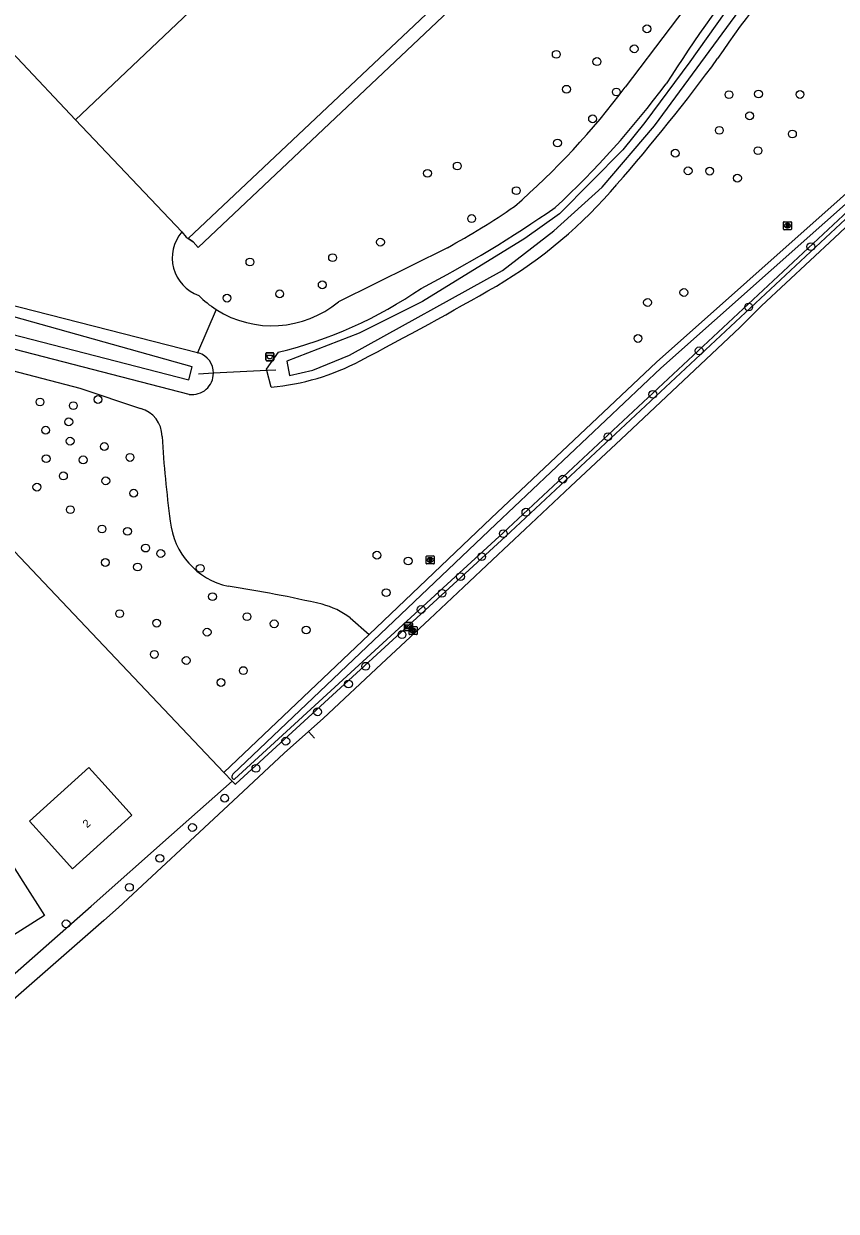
# Model space of a CAD drawing. Extents: x 156651 to 158072, y 387631 to 388990.
# Drawn here: x 157693.9 to 157795.5, y 388128.4 to 388276.8 of the extents above; entities that cross this region are included whole.
import ezdxf

# ---------------------------------------------------------------- set-up
doc = ezdxf.new("R2010")
doc.units = 0
for name, color, linetype in [('IMGEO_Afvalbak', 7, 'Continuous'), ('IMGEO_Boom', 7, 'Continuous'), ('IMGEO_Brandkraan', 7, 'Continuous'), ('IMGEO_Duiker', 7, 'Continuous'), ('IMGEO_Erf', 7, 'Continuous'), ('IMGEO_Grasland_overig', 7, 'Continuous'), ('IMGEO_Greppel_droge_sloot', 7, 'Continuous'), ('IMGEO_Groenvoorziening', 7, 'Continuous'), ('IMGEO_Hek', 7, 'Continuous'), ('IMGEO_Loofbos', 7, 'Continuous'), ('IMGEO_Pand', 7, 'Continuous'), ('IMGEO_Pand_nummerreeks', 7, 'Continuous'), ('IMGEO_Rijbaan_lokaal_gesloten', 7, 'Continuous'), ('IMGEO_Rijbaan_lokaal_open', 7, 'Continuous'), ('IMGEO_Rioolput', 7, 'Continuous'), ('IMGEO_Verklikker', 7, 'Continuous'), ('IMGEO_Waterloop', 7, 'Continuous')]:
    doc.layers.add(name, color=color, linetype=linetype)

msp = doc.modelspace()

# ---------------------------------------------------------------- linework, layer by layer
at = {"layer": 'IMGEO_Afvalbak'}
for p, q in [((157724.2, 388234.74), (157724.2, 388235.54)), ((157724.2, 388235.54), (157724.2, 388234.74)), ((157724.3, 388235.64), (157725.09, 388235.64)), ((157725.09, 388235.64), (157724.3, 388235.64)), ((157725.19, 388235.54), (157725.19, 388234.74)), ((157725.19, 388234.74), (157725.19, 388235.54)), ((157725.09, 388234.64), (157724.3, 388234.64)), ((157724.3, 388234.64), (157725.09, 388234.64))]:
    msp.add_line(p, q, dxfattribs=at)
msp.add_lwpolyline([(157724.34, 388235.35), (157725.05, 388235.35), (157724.9, 388234.88), (157724.49, 388234.88), (157724.34, 388235.35)], dxfattribs=at)
for centre, start, end in [((157724.3, 388235.54), 90, 180), ((157724.3, 388235.54), 90, 180), ((157725.09, 388235.54), 0, 90), ((157725.09, 388235.54), 360, 90), ((157724.3, 388234.74), 180, 270), ((157724.3, 388234.74), 180, 270), ((157725.09, 388234.74), 270, 0), ((157725.09, 388234.74), 270, 0)]:
    msp.add_arc(centre, 0.1, start, end, dxfattribs=at)
at = {"layer": 'IMGEO_Boom'}
for centre in [(157771.82, 388276.12), (157770.23, 388273.62), (157760.49, 388272.93), (157765.57, 388272.03), (157761.77, 388268.57), (157768, 388268.23), (157782.07, 388267.9), (157785.77, 388267.98), (157790.95, 388267.92), (157765.03, 388264.87), (157784.65, 388265.25), (157780.87, 388263.43), (157790, 388262.98), (157760.65, 388261.86), (157775.36, 388260.58), (157785.7, 388260.9), (157748.12, 388258.98), (157744.4, 388258.07), (157776.97, 388258.37), (157779.66, 388258.34), (157783.13, 388257.46), (157755.49, 388255.9), (157749.92, 388252.41), (157738.52, 388249.46), (157792.3, 388248.9), (157722.21, 388246.98), (157732.54, 388247.52), (157731.25, 388244.13), (157719.35, 388242.47), (157725.92, 388243), (157776.44, 388243.17), (157771.9, 388241.92), (157784.53, 388241.36), (157770.7, 388237.43), (157778.35, 388235.88), (157772.55, 388230.44), (157695.98, 388229.49), (157700.14, 388229.03), (157703.22, 388229.8), (157696.68, 388225.96), (157699.57, 388227), (157699.74, 388224.6), (157766.96, 388225.16), (157704.02, 388223.92), (157696.75, 388222.4), (157701.37, 388222.25), (157707.22, 388222.56), (157698.9, 388220.25), (157695.59, 388218.85), (157704.2, 388219.63), (157761.32, 388219.85), (157707.68, 388218.09), (157699.77, 388216.03), (157756.7, 388215.71), (157703.73, 388213.61), (157706.91, 388213.32), (157753.87, 388213.03), (157709.17, 388211.23), (157711.07, 388210.55), (157738.08, 388210.34), (157741.99, 388209.61), (157751.17, 388210.15), (157704.14, 388209.43), (157708.17, 388208.86), (157716, 388208.7), (157748.53, 388207.66), (157717.54, 388205.16), (157739.23, 388205.66), (157746.21, 388205.57), (157743.61, 388203.55), (157705.93, 388203.04), (157721.85, 388202.66), (157710.55, 388201.85), (157716.86, 388200.72), (157725.24, 388201.77), (157729.24, 388201), (157741.21, 388200.42), (157710.26, 388197.94), (157714.25, 388197.18), (157736.68, 388196.46), (157721.39, 388195.92), (157718.59, 388194.43), (157734.52, 388194.25), (157730.66, 388190.76), (157726.69, 388187.1), (157722.96, 388183.7), (157719.05, 388179.97), (157715.03, 388176.31), (157710.95, 388172.46), (157707.15, 388168.84), (157699.24, 388164.28)]:
    msp.add_circle(centre, 0.489, dxfattribs=at)
at = {"layer": 'IMGEO_Brandkraan'}
for p, q in [((157742.1, 388200.49), (157742.1, 388201.34)), ((157742.17, 388201.41), (157743.02, 388201.41)), ((157742.59, 388201.19), (157742.61, 388201.19)), ((157743.1, 388201.34), (157743.1, 388200.49)), ((157743.02, 388200.41), (157742.17, 388200.41)), ((157742.61, 388200.63), (157742.58, 388200.63))]:
    msp.add_line(p, q, dxfattribs=at)
for points in [[(157742.1, 388200.49), (157742.1, 388201.34)], [(157742.17, 388201.41), (157743.02, 388201.41)], [(157742.44, 388201.11), (157742.44, 388200.71), (157742.66, 388200.71)], [(157742.68, 388201.11), (157742.44, 388201.11)], [(157743.1, 388201.34), (157743.1, 388200.49)], [(157743.02, 388200.41), (157742.17, 388200.41)], [(157742.62, 388201.03), (157742.57, 388201.03), (157742.57, 388200.96)], [(157742.57, 388200.96), (157742.62, 388200.96)], [(157742.63, 388200.88), (157742.57, 388200.88), (157742.57, 388200.8)], [(157742.57, 388200.8), (157742.63, 388200.8)]]:
    msp.add_lwpolyline(points, dxfattribs=at)
for centre, radius, start, end in [((157742.17, 388201.34), 0.0765, 91.552, 178.448), ((157742.17, 388201.34), 0.0765, 91.552, 178.448), ((157742.68, 388200.97), 0.145, 59.4692, 91.5367), ((157742.71, 388201.02), 0.0922, 285.5137, 58.1501), ((157743.02, 388201.34), 0.0765, 1.552, 88.448), ((157743.02, 388201.34), 0.0765, 1.552, 88.448), ((157742.17, 388200.49), 0.0765, 181.552, 268.448), ((157742.17, 388200.49), 0.0765, 181.552, 268.448), ((157742.62, 388200.99), 0.0379, 267.8285, 90.9355), ((157742.63, 388200.84), 0.0404, 269.8759, 90.5077), ((157742.66, 388200.96), 0.251, 268.6676, 293.5347), ((157742.71, 388200.82), 0.105, 301.3115, 78.989), ((157743.02, 388200.49), 0.0765, 271.552, 358.448), ((157743.02, 388200.49), 0.0765, 271.552, 358.448)]:
    msp.add_arc(centre, radius, start, end, dxfattribs=at)
for centre, major_axis, ratio, start_param, end_param in [((157742.58, 388200.91), (-0.387, 0.002), 0.722429, 4.712389, 7.853982), ((157742.61, 388200.91), (-0.39, 0.002), 0.717154, 1.570796, 4.712389)]:
    msp.add_ellipse(centre, major_axis=major_axis, ratio=ratio, start_param=start_param, end_param=end_param, dxfattribs=at)
at = {"layer": 'IMGEO_Duiker'}
msp.add_lwpolyline([(157725.44, 388233.48), (157724.34, 388233.42), (157723.48, 388233.38), (157717.66, 388233.08), (157715.8, 388232.98)], dxfattribs=at)
at = {"layer": 'IMGEO_Erf'}
msp.add_lwpolyline([(157720.01, 388182.1), (157718.96, 388183.18)], dxfattribs=at)
at = {"layer": 'IMGEO_Grasland_overig'}
msp.add_lwpolyline([(157714.48, 388249.93), (157742.73, 388276.53), (157772, 388304.24)], dxfattribs=at)
at = {"layer": 'IMGEO_Greppel_droge_sloot'}
for points in [[(157898.22, 388349.88), (157896.12, 388347.95), (157883.14, 388335.24), (157875.62, 388328.26), (157850.32, 388304.57), (157824.42, 388280.31), (157812.24, 388268.91), (157807.84, 388264.16), (157773.56, 388233.71), (157752.92, 388214.22), (157737.66, 388199.69), (157720.09, 388182.97)], [(157720.27, 388182.34), (157753.86, 388213.13), (157808.21, 388263.87), (157812.84, 388268.47), (157850.82, 388304.16)]]:
    msp.add_lwpolyline(points, dxfattribs=at)
for centre, radius, start, end in [((157720.84, 388182.47), 0.906, 146.5853, 171.9999), ((157720.23, 388182.62), 0.284, 185.1845, 278.9201)]:
    msp.add_arc(centre, radius, start, end, dxfattribs=at)
at = {"layer": 'IMGEO_Groenvoorziening'}
for points in [[(157720.01, 388182.1), (157720.37, 388181.71), (157720.45, 388181.78), (157754.16, 388212.68), (157808.51, 388263.42), (157813.13, 388268.02), (157851.11, 388303.71), (157859.17, 388311.3), (157875.96, 388327.05), (157883.96, 388334.28), (157889.9, 388339.8), (157897.83, 388347.26), (157900.24, 388349.53), (157900.45, 388349.74), (157900.08, 388350.11), (157899.45, 388350.76), (157898.68, 388351.56)], [(157737.09, 388200.43), (157752.35, 388214.95), (157773, 388234.45), (157807.27, 388264.9), (157811.67, 388269.65), (157823.85, 388281.05), (157849.76, 388305.31), (157875.06, 388329), (157882.58, 388335.98), (157895.55, 388348.69), (157898.68, 388351.56)], [(157714.63, 388230.44), (157681.86, 388238.86)], [(157680.96, 388236.41), (157700.97, 388231.21), (157708.54, 388228.69)], [(157715.66, 388235.65), (157715.78, 388235.62)], [(157724.87, 388231.33), (157724.34, 388233.42), (157724.3, 388233.57), (157725.76, 388235.71)], [(157718.96, 388183.18), (157670.96, 388233.81)], [(157734.72, 388202.5), (157737.09, 388200.43)], [(157737.09, 388200.43), (157718.96, 388183.18)], [(157691.12, 388156.56), (157702.36, 388166.5), (157712.43, 388175.4), (157720.01, 388182.1)]]:
    msp.add_lwpolyline(points, dxfattribs=at)
for centre, radius, start, end in [((157868.74, 388213.66), 105.88, 135.6314, 146.3009), ((157962.63, 388148.26), 223.91, 142.1451, 147.2893), ((157594.17, 388408.93), 231.12, 318.7989, 323.7926), ((157682.33, 388337.68), 114.57, 312.9233, 323.3326), ((157723.08, 388294.68), 58.88, 300.5528, 319.8157), ((157671.2, 388382.45), 156.53, 297.5526, 304.7184), ((157712.97, 388288.42), 54.23, 283.6398, 304.4018), ((157497.79, 388689.21), 513.2, 297.6555, 299.8223), ((157715, 388233.08), 2.66, 359.9979, 72.8569), ((157722.25, 388260.5), 29.28, 275.133, 297.9998), ((157714.99, 388233.08), 2.66, 262.1888, 0.0084), ((157707.61, 388225.19), 3.62, 359.9494, 75.0421), ((157847.53, 388232.98), 136.52, 183.2751, 187.7468), ((157721.52, 388215.55), 9.32, 185.9724, 257.459), ((157697.89, 388062.38), 145.69, 76.7663, 81.4691), ((157728.98, 388195.17), 9.31, 51.9482, 75.9543)]:
    msp.add_arc(centre, radius, start, end, dxfattribs=at)
at = {"layer": 'IMGEO_Hek'}
for points in [[(157714.48, 388249.93), (157715.11, 388249.5), (157715.75, 388248.8), (157773.13, 388303.04)], [(157700.43, 388264.76), (157713.69, 388250.74)], [(157713.69, 388250.74), (157714.23, 388250.09), (157714.48, 388249.93)]]:
    msp.add_lwpolyline(points, dxfattribs=at)
at = {"layer": 'IMGEO_Loofbos'}
for points in [[(157772, 388304.24), (157773.13, 388303.04), (157715.75, 388248.8), (157715.11, 388249.5), (157714.48, 388249.93)], [(157780.36, 388283.71), (157769.12, 388268.84)], [(157700.43, 388264.76), (157713.69, 388250.74)], [(157713.69, 388250.74), (157714.23, 388250.09), (157714.48, 388249.93)], [(157746.88, 388248.77), (157733.27, 388242.01)], [(157715.66, 388235.65), (157678.64, 388245.1)], [(157717.99, 388241.05), (157715.66, 388235.65)]]:
    msp.add_lwpolyline(points, dxfattribs=at)
for centre, radius, start, end in [((157693.03, 388325.62), 94.94, 310.9512, 323.2697), ((157698.75, 388336.43), 100.01, 298.7674, 304.4049), ((157717.52, 388247.5), 5.02, 139.7833, 250.0185), ((157724.99, 388252.04), 13.03, 225.2117, 237.4879), ((157724.97, 388252.01), 13, 237.5051, 309.712)]:
    msp.add_arc(centre, radius, start, end, dxfattribs=at)
at = {"layer": 'IMGEO_Pand'}
for points in [[(157692.42, 388273.24), (157660.73, 388306.77), (157663.25, 388309.16), (157664.82, 388307.49), (157679.51, 388321.39), (157677.94, 388323.06), (157678.7, 388323.78), (157680.26, 388322.13), (157683.43, 388325.13), (157684.77, 388323.72), (157685.77, 388324.68), (157722.55, 388285.76), (157700.43, 388264.76)], [(157700.43, 388264.76), (157693.11, 388272.51), (157692.42, 388273.24)], [(157702.08, 388183.8), (157704.1, 388181.57), (157707.46, 388177.86), (157700.05, 388171.16), (157696.69, 388174.86), (157694.66, 388177.09), (157702.08, 388183.8)], [(157689.82, 388175.84), (157693.83, 388169.55), (157696.52, 388165.33), (157691.88, 388162.37), (157689.19, 388166.58), (157685.17, 388172.87), (157689.82, 388175.84)]]:
    msp.add_lwpolyline(points, dxfattribs=at)
at = {"layer": 'IMGEO_Rijbaan_lokaal_gesloten'}
for points in [[(157901.9, 388350.55), (157898.23, 388346.86), (157851.76, 388303.15), (157795.28, 388250), (157786.13, 388241.5), (157783.41, 388238.79), (157768.62, 388224.85), (157762.28, 388218.91), (157756.59, 388213.58), (157752.53, 388209.75), (157748.88, 388206.34), (157744.63, 388202.35), (157738.66, 388196.76), (157731.37, 388189.93), (157729.53, 388188.29)], [(157729.53, 388188.29), (157730.29, 388187.49)]]:
    msp.add_lwpolyline(points, dxfattribs=at)
at = {"layer": 'IMGEO_Rijbaan_lokaal_open'}
msp.add_lwpolyline([(157729.53, 388188.29), (157726.48, 388185.59), (157719.5, 388179.05), (157705.8, 388166.31), (157703.95, 388164.69), (157659.96, 388126.22)], dxfattribs=at)
at = {"layer": 'IMGEO_Rioolput'}
for p, q in [((157788.88, 388251.09), (157788.88, 388251.95)), ((157788.95, 388252.02), (157789.81, 388252.02)), ((157789.37, 388251.8), (157789.39, 388251.8)), ((157789.88, 388251.95), (157789.88, 388251.09)), ((157789.81, 388251.02), (157788.95, 388251.02)), ((157789.39, 388251.24), (157789.37, 388251.24)), ((157744.23, 388209.32), (157744.23, 388210.17)), ((157744.31, 388210.25), (157745.16, 388210.25)), ((157744.72, 388210.03), (157744.75, 388210.03)), ((157745.24, 388210.17), (157745.24, 388209.32)), ((157745.16, 388209.25), (157744.31, 388209.25)), ((157744.74, 388209.47), (157744.72, 388209.47))]:
    msp.add_line(p, q, dxfattribs=at)
for points in [[(157788.88, 388251.09), (157788.88, 388251.95)], [(157788.95, 388252.02), (157789.81, 388252.02)], [(157789.47, 388251.72), (157789.22, 388251.72), (157789.22, 388251.32)], [(157789.4, 388251.64), (157789.34, 388251.64), (157789.34, 388251.56)], [(157789.34, 388251.56), (157789.39, 388251.56)], [(157789.88, 388251.95), (157789.88, 388251.09)], [(157789.81, 388251.02), (157788.95, 388251.02)], [(157789.22, 388251.32), (157789.34, 388251.32), (157789.34, 388251.48), (157789.35, 388251.48)], [(157789.4, 388251.45), (157789.47, 388251.32), (157789.61, 388251.32), (157789.54, 388251.45)], [(157744.23, 388209.32), (157744.23, 388210.17)], [(157744.31, 388210.25), (157745.16, 388210.25)], [(157745.24, 388210.17), (157745.24, 388209.32)], [(157745.16, 388209.25), (157744.31, 388209.25)], [(157744.82, 388209.95), (157744.57, 388209.95), (157744.57, 388209.55)], [(157744.57, 388209.55), (157744.7, 388209.55), (157744.7, 388209.71), (157744.71, 388209.71)], [(157744.75, 388209.87), (157744.7, 388209.87), (157744.7, 388209.79)], [(157744.7, 388209.79), (157744.75, 388209.79)], [(157744.75, 388209.68), (157744.82, 388209.55), (157744.96, 388209.55), (157744.9, 388209.67)]]:
    msp.add_lwpolyline(points, dxfattribs=at)
for centre, radius, start, end in [((157788.96, 388251.94), 0.0765, 91.552, 178.448), ((157788.96, 388251.94), 0.0765, 91.552, 178.448), ((157789.38, 388251.75), 0.19, 274.7715, 282.9687), ((157789.4, 388251.54), 0.0964, 77.0061, 93.1865), ((157789.42, 388251.6), 0.0378, 276.6634, 79.6772), ((157789.47, 388251.61), 0.109, 350.3612, 89.416), ((157789.47, 388251.61), 0.112, 277.5842, 350.9817), ((157789.8, 388251.94), 0.0765, 1.552, 88.448), ((157789.8, 388251.94), 0.0765, 1.552, 88.448), ((157788.96, 388251.09), 0.0765, 181.552, 268.448), ((157788.96, 388251.09), 0.0765, 181.552, 268.448), ((157789.35, 388251.43), 0.0533, 26.0293, 88.6989), ((157789.45, 388251.39), 0.108, 29.5134, 73.7905), ((157789.8, 388251.09), 0.0765, 271.552, 358.448), ((157789.8, 388251.09), 0.0765, 271.552, 358.448), ((157744.31, 388210.17), 0.0765, 91.552, 178.448), ((157744.31, 388210.17), 0.0765, 91.552, 178.448), ((157745.16, 388210.17), 0.0765, 1.552, 88.448), ((157745.16, 388210.17), 0.0765, 1.552, 88.448), ((157744.31, 388209.32), 0.0765, 181.552, 268.448), ((157744.31, 388209.32), 0.0765, 181.552, 268.448), ((157744.7, 388209.66), 0.0533, 26.0293, 88.6989), ((157744.75, 388209.77), 0.0964, 77.0061, 93.1865), ((157744.73, 388209.98), 0.19, 274.7715, 282.9687), ((157744.77, 388209.83), 0.0378, 276.6634, 79.6772), ((157744.82, 388209.84), 0.109, 350.3612, 89.416), ((157744.82, 388209.84), 0.112, 277.5842, 350.9817), ((157744.8, 388209.62), 0.108, 29.5134, 73.7905), ((157745.16, 388209.32), 0.0765, 271.552, 358.448), ((157745.16, 388209.32), 0.0765, 271.552, 358.448)]:
    msp.add_arc(centre, radius, start, end, dxfattribs=at)
for centre, major_axis, ratio, start_param, end_param in [((157789.37, 388251.52), (-0.387, 0.002), 0.722429, 4.712389, 7.853982), ((157789.39, 388251.52), (-0.39, 0.002), 0.717154, 1.570796, 4.712389), ((157744.72, 388209.75), (-0.387, 0.002), 0.722429, 4.712389, 7.853982), ((157744.75, 388209.75), (-0.39, 0.002), 0.717154, 1.570796, 4.712389)]:
    msp.add_ellipse(centre, major_axis=major_axis, ratio=ratio, start_param=start_param, end_param=end_param, dxfattribs=at)
at = {"layer": 'IMGEO_Verklikker'}
for p, q in [((157741.53, 388201.01), (157741.53, 388201.81)), ((157741.53, 388201.81), (157741.53, 388201.01)), ((157741.63, 388201.91), (157742.42, 388201.91)), ((157742.42, 388201.91), (157741.63, 388201.91)), ((157742.52, 388201.81), (157742.52, 388201.01)), ((157742.52, 388201.01), (157742.52, 388201.81)), ((157742.42, 388200.91), (157741.63, 388200.91)), ((157741.63, 388200.91), (157742.42, 388200.91))]:
    msp.add_line(p, q, dxfattribs=at)
for points in [[(157741.63, 388201.65), (157742.41, 388201.65), (157742.41, 388201.18), (157741.63, 388201.18), (157741.63, 388201.65)], [(157741.69, 388201.58), (157741.69, 388201.25), (157742.35, 388201.25), (157742.35, 388201.58), (157741.69, 388201.58)]]:
    msp.add_lwpolyline(points, dxfattribs=at)
for centre, start, end in [((157741.63, 388201.81), 90, 180), ((157741.63, 388201.81), 90, 180), ((157742.42, 388201.81), 0, 90), ((157742.42, 388201.81), 360, 90), ((157741.63, 388201.01), 180, 270), ((157741.63, 388201.01), 180, 270), ((157742.42, 388201.01), 270, 0), ((157742.42, 388201.01), 270, 0)]:
    msp.add_arc(centre, 0.1, start, end, dxfattribs=at)
at = {"layer": 'IMGEO_Waterloop'}
for points in [[(157782.6, 388279.64), (157777.19, 388271.99), (157771.57, 388264.42), (157768.79, 388260.98), (157760.91, 388253.01), (157756.55, 388249.94), (157743.79, 388242.04), (157735.87, 388238.1), (157726.83, 388234.6)], [(157726.83, 388234.6), (157727.16, 388232.8), (157730.06, 388233.46), (157734.65, 388235.35), (157753.77, 388245.91), (157760.18, 388250.86), (157766.21, 388256.34), (157772.77, 388263.99), (157783.89, 388279.13)], [(157684.51, 388240.01), (157714.57, 388232.27), (157714.98, 388233.89), (157682.71, 388242.93)]]:
    msp.add_lwpolyline(points, dxfattribs=at)

# ---------------------------------------------------------------- texts
at = {"layer": 'IMGEO_Pand_nummerreeks'}
msp.add_text('2', height=1, rotation=42.1224, dxfattribs=at).set_placement((157701.86, 388176.19))

doc.saveas('drawing.dxf')
